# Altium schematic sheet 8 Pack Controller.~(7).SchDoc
size B; PageSetup: Record=PageOptions|CenterHorizontal=True|CenterVertical=True|PrintScale=1.09|XCorrection=1.00|YCorrection=1.00|PrintKind=0|BorderSize=5000000|LeftOffset=0|BottomOffset=0|Orientation=2|PaperLength=1000|PaperWidth=1000|Scale=100|PaperSource=15|PrintQuality=600|MediaType=1|DitherType=10|PaperKind=11x17|PrintScaleMode=1
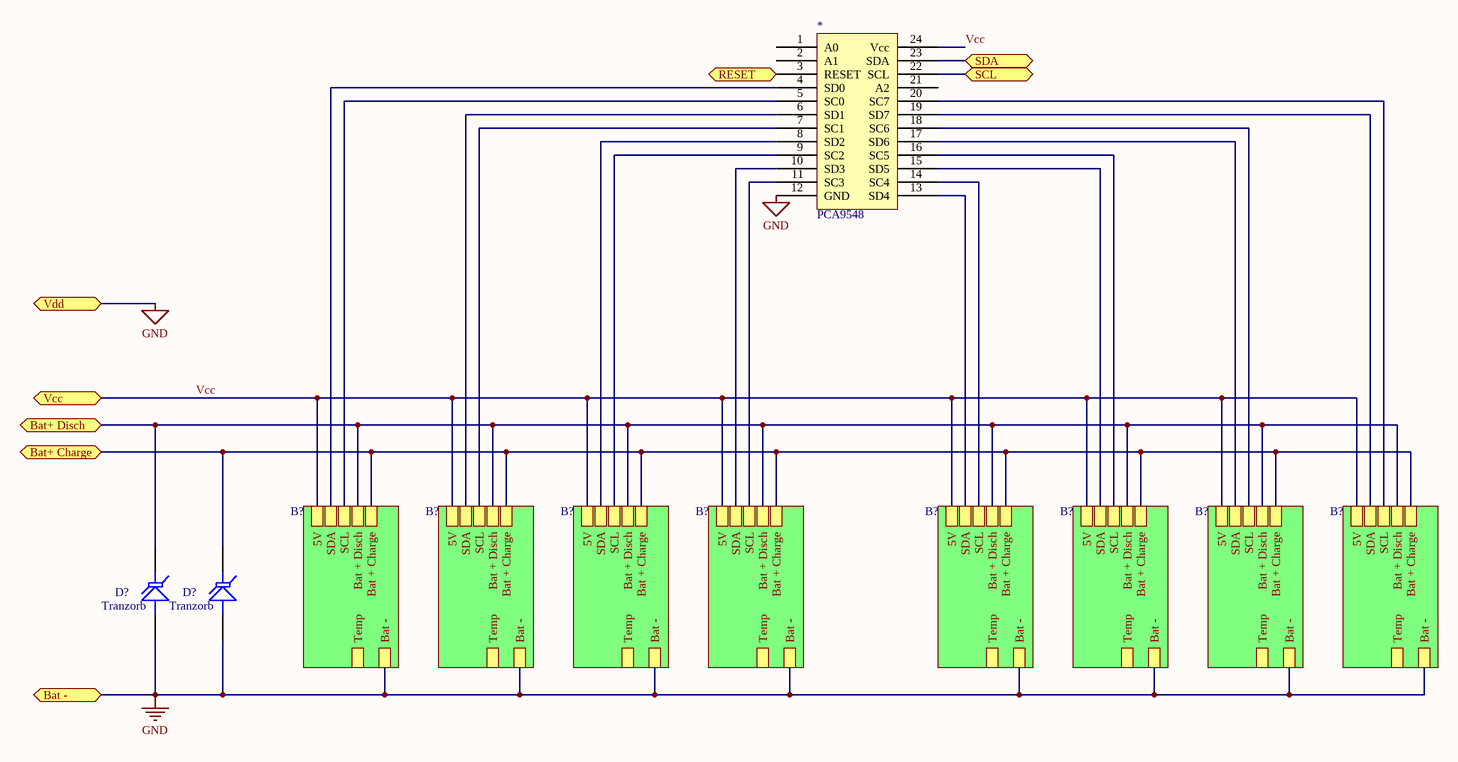
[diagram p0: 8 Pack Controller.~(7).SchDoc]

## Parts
(Parts that share a designator on the sheet are numbered #1, #2 ... from top to bottom, then left to right.)
*  PCA9548
D?#1  Tranzorb  [DIO10.2-7x2.7]
D?#2  Tranzorb  [DIO10.2-7x2.7]

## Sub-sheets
B? = Single Pack Control.SchDoc: Bat -, SCL, SDA, 5V, Temp, Bat + Disch, Bat + Charge
B? = Single Pack Control.SchDoc: Bat -, SCL, SDA, 5V, Temp, Bat + Disch, Bat + Charge
B? = Single Pack Control.SchDoc: Bat -, SCL, SDA, 5V, Temp, Bat + Disch, Bat + Charge
B? = Single Pack Control.SchDoc: Bat -, SCL, SDA, 5V, Temp, Bat + Disch, Bat + Charge
B? = Single Pack Control.SchDoc: Bat -, SCL, SDA, 5V, Temp, Bat + Disch, Bat + Charge
B? = Single Pack Control.SchDoc: Bat -, SCL, SDA, 5V, Temp, Bat + Disch, Bat + Charge
B? = Single Pack Control.SchDoc: Bat -, SCL, SDA, 5V, Temp, Bat + Disch, Bat + Charge
B? = Single Pack Control.SchDoc: Bat -, SCL, SDA, 5V, Temp, Bat + Disch, Bat + Charge

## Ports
Bat - (bidir), Bat+ Charge, Bat+ Disch, RESET (in), SCL, SDA, Vcc, Vdd

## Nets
GND: *.12(GND) D?#1.1(A) D?#2.1(A) ; port Bat -, port Vdd, sheet B?/Bat -, sheet B?/Bat -, sheet B?/Bat -, sheet B?/Bat -, sheet B?/Bat -, sheet B?/Bat -, sheet B?/Bat -, sheet B?/Bat -
Bat+ Charge: D?#2.2(K) ; port Bat+ Charge, sheet B?/Bat + Charge, sheet B?/Bat + Charge, sheet B?/Bat + Charge, sheet B?/Bat + Charge, sheet B?/Bat + Charge, sheet B?/Bat + Charge, sheet B?/Bat + Charge, sheet B?/Bat + Charge
Bat+ Disch: D?#1.2(K) ; port Bat+ Disch, sheet B?/Bat + Disch, sheet B?/Bat + Disch, sheet B?/Bat + Disch, sheet B?/Bat + Disch, sheet B?/Bat + Disch, sheet B?/Bat + Disch, sheet B?/Bat + Disch, sheet B?/Bat + Disch
RESET: *.3(RESET) ; port RESET
SCL: *.22(SCL) ; port SCL
SDA: *.23(SDA) ; port SDA
Vcc: *.24(Vcc) ; port Vcc, sheet B?/5V, sheet B?/5V, sheet B?/5V, sheet B?/5V, sheet B?/5V, sheet B?/5V, sheet B?/5V, sheet B?/5V
Net*_4: *.4(SD0) ; sheet B?/SDA
Net*_5: *.5(SC0) ; sheet B?/SCL
Net*_6: *.6(SD1) ; sheet B?/SDA
Net*_7: *.7(SC1) ; sheet B?/SCL
Net*_8: *.8(SD2) ; sheet B?/SDA
Net*_9: *.9(SC2) ; sheet B?/SCL
Net*_10: *.10(SD3) ; sheet B?/SDA
Net*_11: *.11(SC3) ; sheet B?/SCL
Net*_13: *.13(SD4) ; sheet B?/SDA
Net*_14: *.14(SC4) ; sheet B?/SCL
Net*_15: *.15(SD5) ; sheet B?/SDA
Net*_16: *.16(SC5) ; sheet B?/SCL
Net*_17: *.17(SD6) ; sheet B?/SDA
Net*_18: *.18(SC6) ; sheet B?/SCL
Net*_19: *.19(SD7) ; sheet B?/SDA
Net*_20: *.20(SC7) ; sheet B?/SCL

Not connected (* = marked no-connect by the designer): * 1(A0) 2(A1) 21(A2)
